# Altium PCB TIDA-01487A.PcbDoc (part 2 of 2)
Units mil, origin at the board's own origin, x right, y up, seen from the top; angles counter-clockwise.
Board outline 3500 x 2800 mil, 4 copper layers (Top Layer, GND, VDD, Bottom Layer), stack 61.6 mil thick; 82 components, 45 nets, 239 pads, 112 vias.
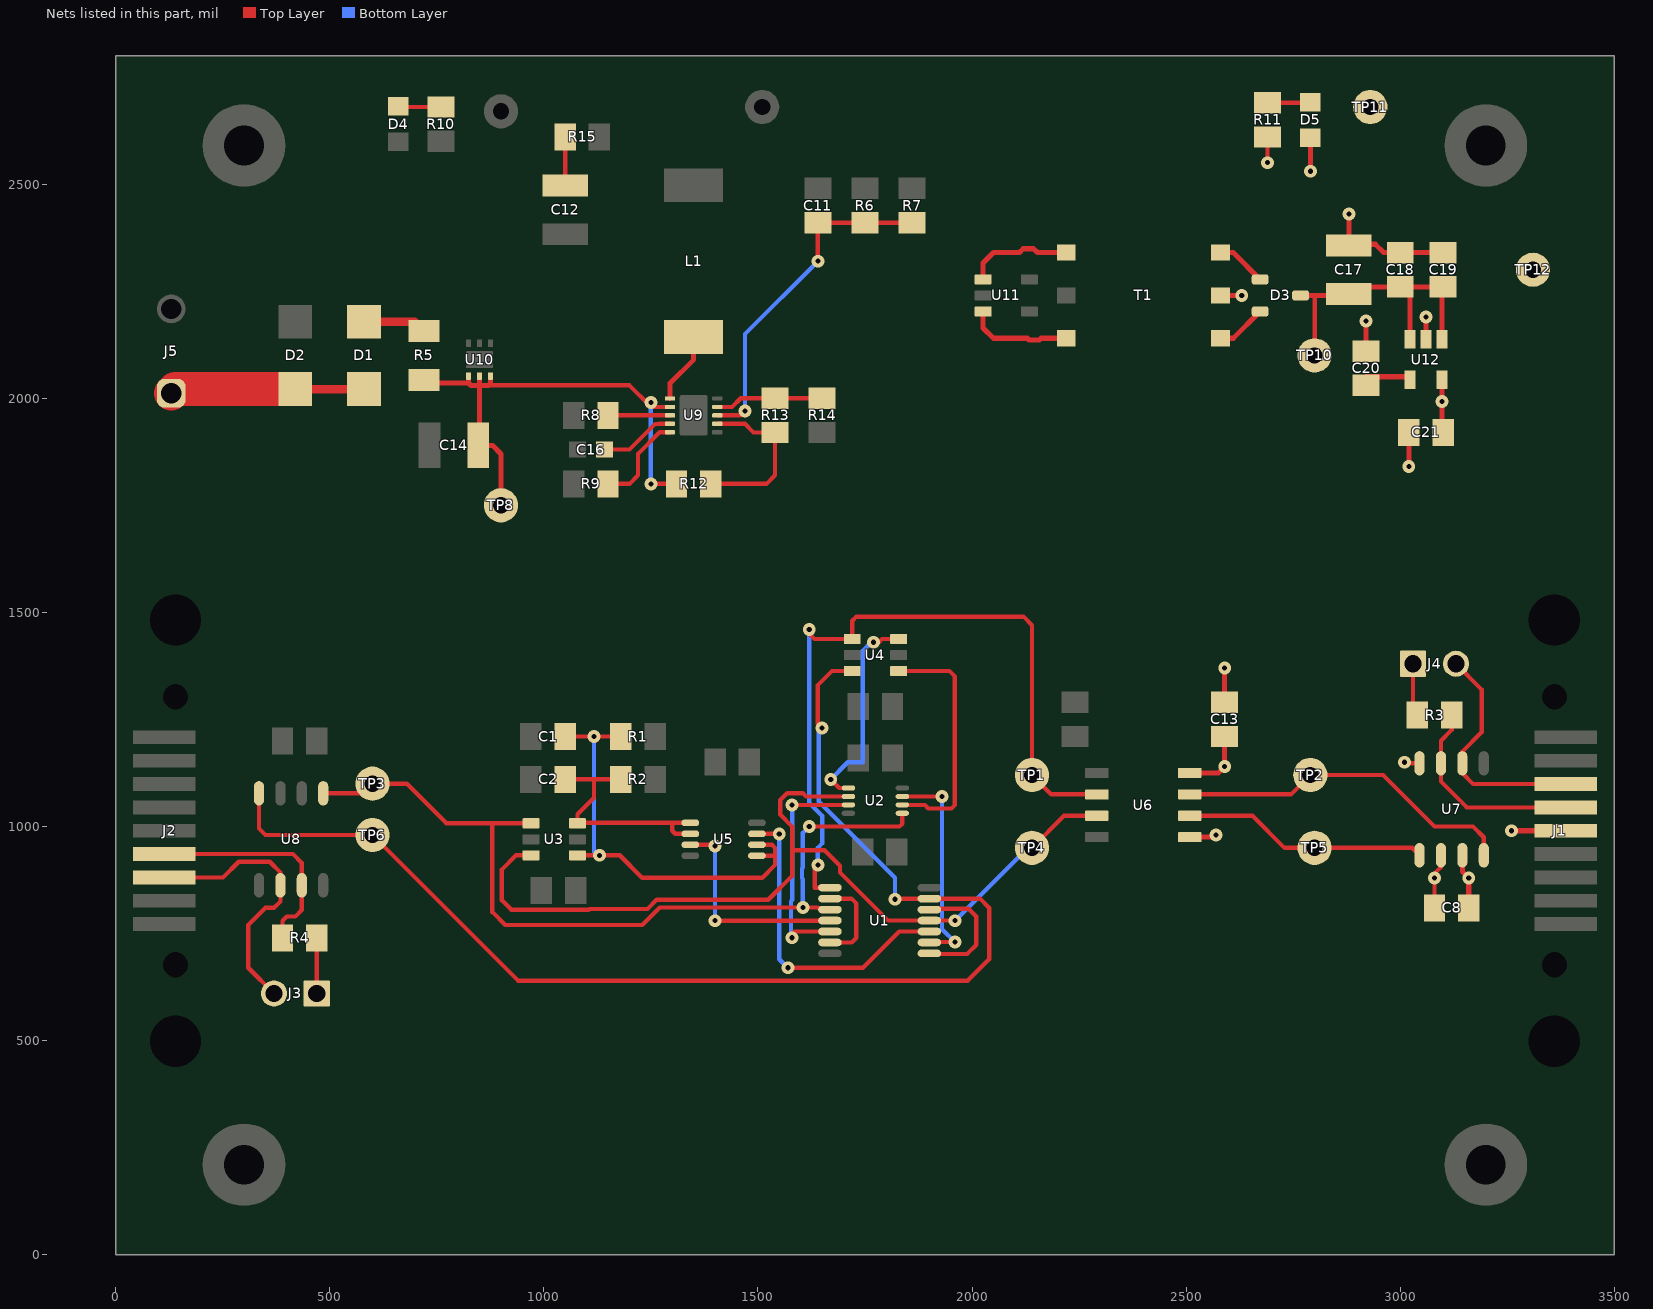
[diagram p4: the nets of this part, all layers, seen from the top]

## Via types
v1: diameter 30, hole 12, Top Layer to Bottom Layer, 79 vias
v2: diameter 39.37, hole 19.68, Top Layer to Bottom Layer, 24 vias
v3: diameter 19.68, hole 7.87, Top Layer to Bottom Layer, 6 vias
v4: diameter 50, hole 20, Top Layer to Bottom Layer, 3 vias

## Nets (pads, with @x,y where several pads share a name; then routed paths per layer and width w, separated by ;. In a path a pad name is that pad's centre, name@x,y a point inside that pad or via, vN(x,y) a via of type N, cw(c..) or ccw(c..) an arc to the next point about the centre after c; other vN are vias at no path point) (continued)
ISO_5V: C8.1 C13.1 C21.1 R11.2 TP11.1 U6.8 U7.3 U12.5 | length 440.7
  Top Layer w10: v1(2690,2550) R11.2@2690,2610
  Top Layer w12: U6.8@2508.27,1125 2575,1125 v1(2590,1140) C13.1@2590,1210 ; U12.5@3097.4,2042.76 v1(3097.4,1992.68) 3097.4,1942.6 C21.1@3100,1940 ; U7.3@3145,932.72 3145,895 v1(3160,880) C8.1@3160,820
ISO_GND: C8.2 C13.2 C17.2 C18.2 C19.2 C20.2 C21.2 D5.1 J1.3 T1.5 TP12.1 U6.5 U7.2 U7.8 U12.2 | length 1077.8
  Top Layer w10: v1(3010,1150) 3012.72,1147.28 U7.8@3045,1147.28 ; C8.2@3080,820 v1(3080,880) 3080,890 3095,905 U7.2@3095,932.72
  Top Layer w12: U6.5@2508.27,975 2565,975 v1(2570,980) ; T1.5@2580,2240 v1(2630,2240) ; C13.2@2590,1290 v1(2590,1370) ; v1(2790,2530) D5.1@2790,2608.66 ; v1(2880,2430) C17.2@2880,2357.09 2882.41,2359.49 2941.72,2359.49 2961.22,2340 C18.2@3000,2340 C19.2@3100,2340 ; C20.2@2920,2130 v1(2920,2180) ; v1(3020,1840.5) C21.2@3020,1920 C21.2@3020,1940 ; U12.2@3060,2137.24 v1(3060,2190) ; v1(3260,990) J1.3@3406,990
NetC1_2: C1.2 R1.1 U3.4 U5.5 U5.6 | length 1015.3
  Top Layer w10: C1.2@1064.41,1210 v1(1117.2,1210) R1.1@1170,1210 ; U3.4@1078.54,932.6 v1(1130,932.6) 1177.4,932.6 1230,880 1510,880 1540,910 1540,950 1532.8,957.2 U5.6@1497.76,957.2 ; U5.5@1497.76,931.61 1538.01,931.61
  Bottom Layer w10: v1(1117.2,1210) 1117.2,935.39 1120,932.6 v1(1130,932.6)
NetC2_2: C2.2 R2.1 U3.6 U5.1 U5.2 | length 551.9
  Top Layer w10: C2.2@1064.41,1110 1117.2,1110 ; R2.1@1170,1110 1117.2,1110 ; U5.2@1342.24,982.8 1307.2,982.8 1300,990 1300,1008.39 ; U5.1@1342.24,1008.39 1300,1008.39 ; 1117.2,1110 1117.2,1067.2 1078.54,1028.54 U3.6@1078.54,1007.4 1079.53,1008.39 1300,1008.39
NetC11_2: C11.2 R6.1 R7.2 U9.8 | length 809.4
  Top Layer w10: U9.8@1405.12,1960 1460,1960 v1(1470,1970) v1@1470,1960 ; v1(1640,2320) C11.2@1640,2410 R7.2@1860,2410
  Bottom Layer w10: v1(1470,1970) 1470,2150 v1(1640,2320)
NetC12_1: C12.1 R15.1 | length 112.9
  Top Layer w10: C12.1@1050,2497.09 R15.1@1050,2610
NetC14_1: C14.1 R5.2 R12.1 TP8.1 U9.2 U10.4 U10.5 U10.6 | length 1227.3
  Top Layer w10: 871.18,2030 1200,2030 v1@1245,1985 ; v1(1250,1800) R12.1@1310,1800 ; v1@1250.31,1979.69 U9.2@1294.88,1979.69
  Top Layer w12: R5.2@720,2042.91 727.32,2035.59 824.41,2035.59 ; U10.4@824.41,2051.61 824.41,2035.59 ; U10.5@850,2051.61 850,2030 ; U10.6@875.59,2051.61 875.59,2034.41 871.18,2030 850,2030 ; TP8.1@900,1750 900,1870 880,1890 C14.1@847.09,1890 850,1892.91 850,2030 ; 824.41,2035.59 830,2030 850,2030
  Bottom Layer w10: v1(1250,1800) 1250,1979.37 1250.31,1979.69 1250.31,1989.69 v1(1250,1990)
NetC16_1: C16.1 U9.4 | length 178.4
  Top Layer w10: C16.1@1141.5,1880 1200,1880 1260,1940 1270,1940 1270.32,1940.32 U9.4@1294.88,1940.32
NetC17_1: C17.1 C18.1 C19.1 D3.3 TP10.1 U12.1 U12.3 | length 737
  Top Layer w10: TP10.1@2800,2100 2800,2240
  Top Layer w12: D3.3@2767.24,2240 2800,2240 2877.09,2240 C17.1@2880,2242.91 2897.09,2260 C18.1@3000,2260 ; U12.3@3022.6,2137.24 3022.6,2237.4 C18.1@3000,2260 ; U12.1@3097.4,2137.24 3097.4,2257.4 C19.1@3100,2260 C18.1@3000,2260
NetC20_1: C20.1 U12.4 | length 105.6
  Top Layer w12: C20.1@2920,2050 3015.35,2050 U12.4@3022.6,2042.76
NetD1_1: D1.1 R5.1 | length 149
  Top Layer w20: D1.1@580,2178.74 698.35,2178.74 R5.1@720,2157.09
NetD1_2: D1.2 D2.2 J5.1 | length 454
  Top Layer w20: D2.2@420,2021.26 D1.2@580,2021.26
  Top Layer w80: J5.1@130,2011.57 139.68,2021.26 D2.2@420,2021.26
NetD3_1: D3.1 T1.6 | length 118.7
  Top Layer w12: T1.6@2580,2340 2610.16,2340 D3.1@2672.76,2277.4
NetD3_2: D3.2 T1.4 | length 118.7
  Top Layer w12: T1.4@2580,2140 2610.16,2140 D3.2@2672.76,2202.6
NetD4_2: D4.2 R10.1 | length 100.6
  Top Layer w10: D4.2@660,2681.34 661.34,2680 R10.1@760,2680
NetD5_2: D5.2 R11.1 | length 100.6
  Top Layer w10: R11.1@2690,2690 2788.66,2690 D5.2@2790,2691.34
NetJ1_2: J1.2 J4.2 U7.6 | length 570.7
  Top Layer w10: J4.2@3130,1380 3190,1320 3190,1220 3145,1175 U7.6@3145,1147.28 3145,1124.17 3170.17,1099 J1.2@3406,1099
NetJ1_7: J1.7 R3.2 U7.7 | length 501.4
  Top Layer w10: R3.2@3120,1260 3120,1225 3095,1200 U7.7@3095,1147.28 3095,1105 3155.5,1044.5 J1.7@3406,1044.5
NetJ2_2: J2.2 J3.2 U8.6 | length 646.8
  Top Layer w10: J2.2@114,881 251,881 287.63,917.63 360,917.63 385,892.63 U8.6@385,862.72 385,825 370,810 350,810 310,770 310,670 J3.2@370,610
NetJ2_7: J2.7 R4.2 U8.7 | length 534.8
  Top Layer w10: J2.7@114,935.5 414.5,935.5 435,915 U8.7@435,862.72 435,805 420,790 400,790 390,780 R4.2@390,740
NetJ3_1: J3.1 R4.1 | length 130
  Top Layer w10: J3.1@470,610 R4.1@470,740
NetJ4_1: J4.1 R3.1 | length 124.1
  Top Layer w10: J4.1@3030,1380 3030,1270 R3.1@3040,1260
NetL1_1: L1.1 U9.1 | length 166.3
  Top Layer w12: U9.1@1294.88,1999.37 1294.88,2034.88 1350,2090 L1.1@1350,2142.83
NetR8_2: R8.2 U9.3 | length 144.9
  Top Layer w10: R8.2@1150,1960 U9.3@1294.88,1960
NetR9_2: R9.2 U9.5 | length 224.1
  Top Layer w10: R9.2@1150,1800 1200,1800 1220,1820 1220,1870 1270.63,1920.63 U9.5@1294.88,1920.63
NetR12_2: R12.2 R13.2 U9.7 | length 401.6
  Top Layer w10: R12.2@1390,1800 1520,1800 1540,1820 R13.2@1540,1920 1490,1920 1469.69,1940.31 U9.7@1405.12,1940.31
NetR13_1: R13.1 R14.2 U9.9 | length 253.3
  Top Layer w10: U9.9@1405.12,1979.68 1439.68,1979.68 1460,2000 R13.1@1540,2000 R14.2@1650,2000
NetT1_1: T1.1 U11.1 | length 250.1
  Top Layer w12: U11.1@2025.87,2277.4 2025.87,2315.87 2050,2340 2110.72,2340 2119.77,2349.05 2143.69,2349.05 2152.75,2340 T1.1@2220,2340
NetT1_3: T1.3 U11.3 | length 245.8
  Top Layer w12: U11.3@2025.87,2202.6 2025.87,2164.13 2050,2140 2129.17,2140 2133.04,2136.13 2156.96,2136.13 2160.83,2140 T1.3@2220,2140
NetTP2_1: TP2.1 U6.7 U7.4 | length 807.7
  Top Layer w10: U6.7@2508.27,1075 2745,1075 TP2.1@2790,1120 2960,1120 3080,1000 3170,1000 3195,975 U7.4@3195,932.72
NetTP5_1: TP5.1 U6.6 U7.1 | length 575
  Top Layer w10: U6.6@2508.27,1025 2655,1025 2730,950 TP5.1@2800,950 3027.72,950 U7.1@3045,932.72
NetU1_2: U1.2 U1.6 | length 212.7
  Top Layer w10: U1.6@1668.26,729.13 1719.13,729.13 1730,740 1730,820 1718.51,831.49 U1.2@1668.26,831.49
NetU1_4: U1.4 U5.3 | length 507.3
  Top Layer w10: U5.3@1342.24,957.2 1402.8,957.2 v1(1400,954.41) ; v1(1400,780) 1667.95,780 U1.4@1668.26,780.31
  Bottom Layer w10: v1(1400,780) v1(1400,954.41)
NetU1_5: U1.5 U2.3 | length 547.6
  Top Layer w10: v1(1580,740) 1580,750 1584.72,754.72 U1.5@1668.26,754.72 ; v1(1580,1050) U2.3@1710.94,1050
  Bottom Layer w10: v1@1577.11,1047.11 v1(1580,1050) 1580,828.23 1577.11,825.34 1577.11,742.89 v1(1580,740)
NetU1_8: U1.8 U1.12 | length 304.2
  Top Layer w10: U1.8@1900.55,703.54 1901.96,702.13 1988.59,702.13 2010,723.54 2010,790 1992.13,807.87 1900.55,807.87 U1.12@1900.55,805.9
NetU1_9: U1.9 U2.7 | length 504.9
  Top Layer w10: U2.7@1837.4,1070.16 1837.56,1070 v1(1930,1070) ; U1.9@1900.55,729.13 1901.42,730 v1(1960,730)
  Bottom Layer w10: v1(1930,1070) 1930,760 v1(1960,730)
NetU1_10: U1.10 U5.7 | length 746.2
  Top Layer w10: U5.7@1497.76,982.8 v1(1550,982.8) v1@1557.2,982.8 ; v1(1570,670) 1745.28,670 1830,754.72 U1.10@1900.55,754.72
  Bottom Layer w10: v1(1550,982.8) 1550,690 v1(1570,670)
NetU2_1: U2.1 U4.6 | length 497.6
  Top Layer w10: v1(1670,1110) 1690.16,1089.84 U2.1@1711.42,1089.84 U2.1@1712.32,1088.94 ; v1(1770,1430) 1782.28,1430 1790,1437.72 U4.6@1828.54,1437.72
  Bottom Layer w10: v1(1670,1110) 1710,1150 1744.72,1150 1744.72,1410 1764.72,1430 v1(1770,1430)
NetU2_6: U2.6 U4.4 | length 566.1
  Top Layer w10: U4.4@1828.54,1362.91 1947.09,1362.91 1960,1350 1960,1050 1952.13,1042.13 1897.87,1042.13 1890,1050 1837.87,1050 U2.6@1837.4,1050.47
RX1: TP6.1 U1.13 U4.3 U8.4 | length 2976.3
  Top Layer w10: U8.4@335,1077.28 335,995 350,980 TP6.1@600,980 940,640 1990,640 2040,690 2040,810 2018.51,831.49 U1.13@1900.55,831.49 1821.49,831.49 v1(1820,830) ; v1(1650,1230) 1640,1240 1640,1330 1672.91,1362.91 U4.3@1720.28,1362.91
  Bottom Layer w10: v1@1642.13,1230 1642.13,1057.98 1820,880.11 v1(1820,830)
RX2_: TP1.1 U1.1 U4.1 U6.2 | length 1768.1
  Top Layer w10: v1(1620,1460) 1620,1450 1632.28,1437.72 U4.1@1720.28,1437.72 1720.28,1480.28 1730,1490 2120,1490 2140,1470 TP1.1@2140,1120 2185,1075 U6.2@2291.73,1075 ; v1(1640,910) 1632.92,902.92 1632.92,857.08 U1.1@1668.26,857.08
  Bottom Layer w10: v1(1620,1460) 1620,1430 1620,1054.83 1650,1024.83 1650,960 1640,950 v1(1640,910)
TX1: TP3.1 U1.3 U2.5 U3.1 U8.1 | length 2001.5
  Top Layer w10: U8.1@485,1077.28 577.28,1077.28 TP3.1@600,1100 680,1100 772.6,1007.4 880,1007.4 ; U3.1@970.28,1007.4 880,1007.4 ; v1(1619.98,1000) 1830.87,1000 1837.4,1006.54 U2.5@1837.4,1030.79 ; U1.3@1668.26,805.9 1664.41,809.76 1640.56,809.76 1639.41,810.91 v1(1604.99,810.91) 1270.91,810.91 1230,770 910,770 880,800 880,1007.4
  Bottom Layer w10: v1(1604.99,810.91) 1604.99,877 1602.99,879 1602.99,902.09 1604.99,904.09 1604.99,985.01 v1(1619.98,1000)
TX2_: TP4.1 U1.11 U2.2 U3.3 U6.3 | length 2123.4
  Top Layer w10: U3.3@970.28,932.6 935.2,932.6 902.13,899.53 902.13,827.87 924.37,805.63 1104.74,805.63 1106.52,807.4 1242.12,807.4 1263.51,828.79 1524.38,828.79 1580,884.4 1580,940 ; U2.2@1711.42,1070.16 1612.67,1070.16 1604.96,1077.87 1568.45,1077.87 1552.13,1061.55 1552.13,1027.87 1580,1000 1580,940 ; v1(1960,780) 1959.69,780.31 U1.11@1900.55,780.31 1804.09,780.31 1691.93,892.48 1691.93,908.07 1655.6,944.4 1584.4,944.4 1580,940 ; TP4.1@2140,950 2215,1025 U6.3@2291.73,1025
  Bottom Layer w10: v1(1960,780) 2130,950 TP4.1@2140,950
pads on no net: J1.1 J1.4 J1.5 J1.6 J1.8 J1.9 J1.MH J2.1 J2.4 J2.5 J2.6 J2.8 J2.9 J2.MH MH1.1 MH2.1 MH3.1 MH4.1 U7.5 U8.5 U9.6 U9.11@1340.16,1899.76 U9.11@1340.16,2020.24 U9.11@1350,1935.2 U9.11@1350,1984.8 U9.11@1359.84,1899.76 U9.11@1359.84,2020.24 U10.7@832.28,2090 U10.7@867.72,2090
copper on no net:
  other v2: 300,138.64 3200,138.64 238.2,174.32 361.8,174.32 3138.2,174.32 3261.8,174.32 238.2,245.68 361.8,245.68 3138.2,245.68 3261.8,245.68 300,281.36 3200,281.36 300,2518.64 3200,2518.64 238.2,2554.32 361.8,2554.32 3138.2,2554.32 3261.8,2554.32 238.2,2625.68 361.8,2625.68 3138.2,2625.68 3261.8,2625.68 300,2661.36 3200,2661.36

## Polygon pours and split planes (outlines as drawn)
GND on GND "GND_POUR" (solid, remove dead copper, pour order 0): 0,2800 2240,2800 2240,1450 2240,1420 2320,1340 2320,0 0,0 0,1890
ISO_GND on GND "GNd_POUR" (solid, remove dead copper, pour order 2): 2550,2800 2550,1420 2480,1350 2480,0 3500,0 3500,2800
5V on VDD "VDD_POUR" (solid, remove dead copper, pour order 6): 0,2800 2240,2800 2240,1420 2320,1340 2320,0 0,0 0,1840 426.58,1840 430,1843.42 430,2360 0,2360
ISO_5V on VDD "VDD_ISO_5V_P008" (solid, remove dead copper, pour order 8): 2550,2800 2550,1420 2550,1418.97 2480,1348.97 2480,0 3500,0 3500,2800

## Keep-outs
Keep-Out Layer:
  text ".Layer_Name" at 577,-858.49 h60

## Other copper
Top Layer:
  text ".Layer_Name" at 577,-858.49 h60
GND:
  pour cut-out: 0,2360 430,2360 430,1843.42 0,1843.42
Bottom Layer:
  text ".Layer_Name" at 577,-858.49 h60

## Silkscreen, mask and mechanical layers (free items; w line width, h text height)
Top Overlay:
  region: 2810,360 2510,360 2510,260 2810,260
  text "GND" at 860,2730 h40
  text "5V" at 1420,2640 h40 r90
  text "ISO_5V" at 3030,2630 h40 r90
  text "ISO_GND" at 3230,2360 h40
  text "'.PRJ_Number'.PCB_Rev-" at 1800,280 h108.27
  text ".Layer_Name" at 577,-858.49 h60
Bottom Overlay:
  text ".Layer_Name" at 577,-858.49 h60
Top Paste:
  text ".Layer_Name" at 577,-858.49 h60
Bottom Paste:
  text ".Layer_Name" at 577,-858.49 h60
Top Solder:
  text ".Layer_Name" at 577,-858.49 h60
  text ".Layer_Name" at 577,-858.49 h60
Bottom Solder:
  text ".Layer_Name" at 577,-858.49 h60
Drill Guide:
  text ".Layer_Name" at 577,-858.49 h60
M1 Board Outline:
  lines w10: 3500,-200 3500,2800 0,2800 0,0 3500,0
  text ".Layer_Name" at 577,-858.49 h60
M2 Board Dimensions:
  rectangle: 125,-400 500,-275
  rectangle: 0,-275 125,-150
  lines w7: 0,-275 1000,-275 ; 125,-400 125,-150 ; 250,-400 250,-150 ; 500,-400 500,-150 ; 750,-400 750,-150 ; 0,-400 0,-150 1000,-150 1000,-400 0,-400
  text ".Layer_Name" at 577,-858.49 h60
M3 3D STEP Top:
  text ".Layer_Name" at 577,-858.49 h60
M4 3D STEP Bottom:
  text ".Layer_Name" at 577,-858.49 h60
M5 Assembly Top:
  lines w10: -292,-930.17 6308,-930.17 ; -292,-726.83 6310,-726.83 ; -292,-523.5 -292,-1133.5 3713,-1133.5 6310,-1133.5 6310,-523.5 -291.5,-523.5 -291.5,-1133.5 1284,-1133.5 ; 2173,-1133.5 2173,-523.5 ; 3440,-726.83 3440,-523.5 ; 4280,-726.83 4280,-523.5 ; 4902,-1140 4902,-937.17
  text "COMPONENTS MARKED 'DNP' SHOULD NOT BE POPULATED." at 1153.5,-318.5 h60
  text "ASSEMBLY VARIANT:" at 1153,-434 h60
  text ".VariantName" at 2189,-434 h60
  text "PCB VIEWED FROM TOP SIDE" at -228.5,-655.67 h60
  text "BOARD #:" at 2248,-655.67 h60
  text ".PRJ_Number" at 2793.5,-655.67 h60
  text "REV:" at 3638,-655.67 h60
  text ".PCB_Rev" at 3929.5,-655.67 h60
  text "SVN REV:" at 4476,-655.67 h60
  text ".VersionControl_RevNumber" at 4982,-655.67 h60
  text "TID #:" at 2248,-859 h60
  text ".TID" at 2793.5,-859 h60
  text "PLOT NAME =" at -228.5,-1064.34 h60
  text ".plot_File_Name" at 577,-1064.34 h60
  text "GENERATED    :" at 2250,-1064.34 h60
  text ".Print_Date" at 3119.5,-1064.34 h60
  text ".Print_Time" at 3848.5,-1064.34 h60
  text "TEXAS INSTRUMENTS" at 5113,-1064.34 h60
M6 Assembly Bottom:
  lines w10: -292.5,-727.33 6309.5,-727.33 ; -290.5,-930.67 6309.5,-930.67 ; 1115.5,-1140.5 1115.5,-937.67 ; 1737.5,-727.33 1737.5,-524 ; 2577.5,-727.33 2577.5,-524 ; 3844.5,-1134 3844.5,-524 ; 4733.5,-1134 6309,-1134 6309,-524 -292.5,-524 -292.5,-1134 2304.5,-1134 6309.5,-1134 6309.5,-524
  text "COMPONENTS MARKED 'DNP' SHOULD NOT BE POPULATED." at 6102,-318 h60
  text ".VariantName" at 5058,-434 h60
  text "ASSEMBLY VARIANT:" at 6097,-434 h60
  text ".VersionControl_RevNumber" at 1035.5,-656.17 h60
  text "SVN REV:" at 1541.5,-656.17 h60
  text ".PCB_Rev" at 2088,-656.17 h60
  text "REV:" at 2379.5,-656.17 h60
  text ".PRJ_Number" at 3224,-656.17 h60
  text "BOARD #:" at 3769.5,-656.17 h60
  text "PCB VIEWED FROM BOTTOM SIDE" at 6246,-656.17 h60
  text ".TID" at 3224,-859.5 h60
  text "TID #:" at 3769.5,-859.5 h60
  text "TEXAS INSTRUMENTS" at 904.5,-1064.84 h60
  text ".Print_Time" at 2169,-1064.84 h60
  text ".Print_Date" at 2898,-1064.84 h60
  text "GENERATED    :" at 3767.5,-1064.84 h60
  text ".plot_File_Name" at 5440.5,-1064.84 h60
  text "PLOT NAME =" at 6246,-1064.84 h60
M9 Title Sheet:
  drawing of 57 lines, arcs and shapes, not listed
  text "1" at 739.84,8036.5 h70
  text "2" at 3235.5,8036.5 h70
  text "3" at 5724.84,8036.5 h70
  text "4" at 8231.51,8036.5 h70
  text "5" at 10730.5,8036.5 h70
  text "6" at 13235.5,8036.5 h70
  text "A" at -416.5,6893.5 h70
  text "A" at 14383.5,6893.5 h70
  text "B" at -416.5,4513.5 h70
  text "B" at 14383.5,4513.5 h70
  text "C" at -416.5,2138.5 h70
  text "C" at 14383.5,2138.5 h70
  text "PROJECT TITLE:" at 11343.5,277.5 h45
  text ".PRJ_Title" at 11393.5,144.17 h70
  text "DESIGNED FOR:" at 11343.5,-23.5 h45
  text ".PRJ_Customer" at 11393.5,-163.5 h70
  text "D" at -416.5,-231.5 h70
  text "D" at 14383.5,-231.5 h70
  text "FILE NAME:" at 11343.5,-323.5 h45
  text ".PCB_File_Name_No_Path" at 11393.5,-443.5 h70
  text "Texas Instruments (TI) and/or its licensors do not warrant the accuracy or completeness of this specification" at 6374,-605.34 h45
  text "ENGINEER:" at 11343.5,-613.5 h45
  text "LAYOUT BY:" at 12848.5,-613.5 h45
  text "or any information contained therein. TI and/or its licensors do not warrant that this design will meet" at 6329.01,-718 h45
  text ".PRJ_Engineer" at 11393.5,-768.49 h70
  text ".PCB_Layout" at 12899,-768.49 h70
  text "the specifications, will be suitable for your application or fit for any particular purpose, or will operate in" at 6329.01,-830.67 h45
  text ".Layer_Name" at 577,-858.49 h60
  text "ALTIUM DESIGNER VERSION:" at 12848.5,-923.5 h45
  text "an implementation. TI and/or its licensors do not warrant that the design is production worthy. You should" at 6329.01,-943.33 h45
  text "completely validate and test your design implementation to confirm the system functionality for your application." at 6374,-1056 h45
  text ".print_Scale" at 11393.5,-1056.83 h70
  text ".Application_BuildNumber" at 12899,-1056.83 h70
  text "1" at 739.84,-1263.5 h70
  text "2" at 3235.5,-1263.5 h70
  text "3" at 5724.84,-1263.5 h70
  text "4" at 8231.51,-1263.5 h70
  text "5" at 10730.5,-1263.5 h70
  text "6" at 13235.5,-1263.5 h70
M10 Fab Notes:
  drawing of 173 lines, arcs and shapes, not listed
  text "DESIGN INFORMATION" at 12378.02,6201 h60
  text "MIN. TRACK WIDTH:" at 11733.46,6021 h60
  text "8" at 12829.7,6021 h60
  text "MIL" at 12984.46,6021 h60
  text "MIN. CLEARANCE:" at 11733.46,5889 h60
  text "0.2" at 12769.7,5889 h60
  text "mm" at 12984.46,5889 h60
  text "MIN. VIA PAD SIZE:" at 11733.46,5757 h60
  text "24" at 12799.71,5757 h60
  text "MIL" at 12984.46,5757 h60
  text "0.05mm (2MIL)" at 12428.46,5615.29 h60
  text "MINIMUM ANNULAR RING" at 11404.23,5611 h60
  text "EXTERNAL" at 13136.46,5611 h60
  text "PER" at 11604.23,5493 h60
  text "IPC-D-275 CLASS 2 LEVEL C" at 11824.23,5493 h60
  text "MIL, HOLES" at 13312.46,5380.71 h60
  text "+/-" at 12920,5380 h60
  text "+/-" at 13774,5380 h60
  text "REGISTRATION TOLERANCES:" at 11404.23,5375 h60
  text "METAL" at 12604,5375 h60
  text "5" at 13180.2,5375 h60
  text "3" at 14013.2,5375 h60
  text "MIL" at 14129.46,5375 h60
  text "+/-" at 13774,5262 h60
  text "HOLE SIZE TOLERANCE (UNLESS OTHERWISE SPECIFIED):" at 11404.23,5257 h60
  text "3" at 14013.2,5257 h60
  text "MIL" at 14129.46,5257 h60
  text "MATERIAL:" at 11329.46,5047.54 h60
  text "FR-4 High Tg" at 12315.9,4907.21 h60
  text "FR-408" at 11750.46,4898.64 h60
  text "OTHER" at 13238.46,4898.64 h60
  text "X" at 12161,4895 h60
  text "62 MIL (1.6mm) +/-10%" at 12070.56,4735.92 h60
  text "THICKNESS:" at 11404.23,4731.64 h60
  text "X" at 11942.4,4731.64 h60
  text "OTHER" at 13355.46,4731.64 h60
  text "TOLERANCE:" at 11404.23,4573.64 h60
  text "X" at 12243.53,4573.64 h60
  text "ANSI IPC-6012 TYPE 3 CLASS 2" at 12430.48,4573.64 h60
  text "OTHER +/-" at 12430.46,4417.64 h60
  text "BOW & TWIST:" at 11404.23,4260.64 h60
  text "X" at 12243.53,4260.64 h60
  text "ANSI IPC-6012 TYPE 3 CLASS 2" at 12430.48,4260.64 h60
  text "OTHER +/-" at 12430.46,4102.13 h60
  text "DRILLING:" at 11329.46,3963.64 h60
  text "REFERENCE:" at 11404.23,3846.64 h60
  text "X" at 12052.46,3846.64 h60
  text "AS SHOWN" at 12239.46,3846.64 h60
  text "X" at 12953.46,3846.64 h60
  text "NC_DRILL FILES" at 13090.46,3846.64 h60
  text "PTH COPPER THICKNESS:" at 11404.23,3688.64 h60
  text "X" at 12534.46,3688.64 h60
  text "20-30 um" at 12671.46,3688.64 h60
  text "OTHER" at 13388.46,3688.64 h60
  text "BOARD FINISH:" at 11329.46,3529.64 h60
  text "SILKSCREEN:" at 11484.68,3411.64 h60
  text "X" at 12433.46,3411.64 h60
  text "TOP" at 12559.46,3411.64 h60
  text "X" at 12943.46,3411.64 h60
  text "BOTTOM" at 13070.46,3411.64 h60
  text "SILKSCREEN COLOR:" at 11484.68,3244.64 h60
  text "X" at 12432.42,3244.64 h60
  text "WHITE" at 12559.46,3244.64 h60
  text "OTHER" at 13070.46,3244.64 h60
  text "X" at 12563.42,3085.44 h60
  text "GREEN" at 12690.46,3085.44 h60
  text "OTHER" at 13308.46,3085.44 h60
  text "SOLDER RESIST COLOR:" at 11484.68,3074.64 h60
  text "X" at 12563.42,2915.44 h60
  text "MATTE" at 12690.46,2915.44 h60
  text "SEMI-GLOSS" at 13308,2914.8 h60
  text "IMMERSION GOLD (ENIG)" at 12390.46,2726.92 h60
  text "ENEPIG" at 13728,2723.64 h60
  text "SURFACE FINISH:" at 11329.46,2722.64 h60
  text "X" at 12203.51,2722.64 h60
  text "IMM. TIN/SILVER OR EQUIV" at 11659,2565.64 h60
  text "OTHER" at 13090.46,2565.64 h60
  text "ARRAY/PANEL:" at 11329.46,2386.64 h60
  text "CUT AND TRIM PER M1 BOARD OUTLINE" at 12390.46,2382.35 h60
  text "N.C. ROUTE" at 12390.46,2230.64 h60
  text "X" at 13069.46,2230.64 h60
  text "V. SCORE" at 13256.46,2230.64 h60
  text "CERTIFICATION:" at 11329.46,2093.64 h60
  text "MATERIALS AND WORKMANSHIP FOR ALL PCBS" at 12054.46,2093.64 h60
  text "TO MEET OR EXCEED THE REQUIREMENTS OF:" at 12054.46,1995.64 h60
  text "X" at 11680.96,1859.13 h60
  text "ANSI IPC-A-600F CLASS ->" at 11819.96,1859.13 h60
  text "X" at 13459.02,1859.13 h60
  text "2" at 13577.96,1859.14 h60
  text "1" at 13262.96,1857.64 h60
  text "3" at 13931.96,1857.64 h60
  text "X" at 12495.02,1699.64 h60
  text "RoHS" at 12631.96,1699.64 h60
  text "OTHER" at 13276.36,1699.64 h60
  text "PER ORDER" at 13673.42,1699.64 h60
  text "ALL BOARDS MUST MEET OR EXCEED UL94-V0 REQUIREMENTS." at 11357,1534 h60
  text "PCB MUST BEAR THE UL94V-0 UL REGISTERED MATERIAL ID NUMBER" at 11357,1414 h60
  text "ADDITIONAL REQUIREMENTS:" at 11329.46,1240.64 h60
  text "MICROSECTION:" at 11404.23,1125.64 h60
  text "YES" at 12309.96,1125.64 h60
  text "REQUIRED" at 13171.46,969.49 h60
  text "BARE BOARD ELEC. TEST:" at 11404.23,966.64 h60
  text "NONE" at 12709.96,966.64 h60
  text "X" at 13044.46,966.64 h60
  text "PER ORDER" at 13763.46,966.64 h60
  text ".Layer_Name" at 577,-858.49 h60
M11 Gerber Information:
  lines w10: -292,-930.17 6308,-930.17 ; -292,-726.83 6310,-726.83 ; -292,-523.5 -292,-1133.5 3713,-1133.5 6310,-1133.5 6310,-523.5 -291.5,-523.5 -291.5,-1133.5 1284,-1133.5 ; 2173,-1133.5 2173,-523.5 ; 3440,-726.83 3440,-523.5 ; 4280,-726.83 4280,-523.5 ; 4902,-1140 4902,-937.17
  text "ALL ARTWORK VIEWED FROM TOP SIDE" at -228.5,-655.67 h60
  text "BOARD #:" at 2248,-655.67 h60
  text ".PRJ_Number" at 2793.5,-655.67 h60
  text "REV:" at 3638,-655.67 h60
  text ".PCB_Rev" at 3929.5,-655.67 h60
  text "SVN REV:" at 4476,-655.67 h60
  text ".VersionControl_RevNumber" at 4982,-655.67 h60
  text "LAYER NAME =" at -228.5,-858.49 h60
  text "TID #:" at 2248,-859 h60
  text ".TID" at 2793.5,-859 h60
  text "PLOT NAME =" at -228.5,-1064.34 h60
  text ".plot_File_Name" at 577,-1064.34 h60
  text "GENERATED    :" at 2250,-1064.34 h60
  text ".Print_Date" at 3119.5,-1064.34 h60
  text ".Print_Time" at 3848.5,-1064.34 h60
  text "TEXAS INSTRUMENTS" at 5113,-1064.34 h60
M12 Stackup:
  drawing of 295 lines, arcs and shapes, not listed
  text "Layer" at 9797.84,7830 h60
  text "Name" at 10207.76,7830 h60
  text "Material" at 11137.5,7830 h60
  text "Thickness" at 11997.27,7830 h60
  text "Constant" at 12647.1,7830 h60
  text "Board Layer Stack" at 13216.96,7830 h60
  text "1" at 9797.84,7710 h60
  text "Top Overlay" at 10207.76,7710 h60
  text "2" at 9797.84,7590 h60
  text "Top Solder" at 10207.76,7590 h60
  text "Solder Resist" at 11137.5,7590 h60
  text "0.40mil" at 11997.27,7590 h60
  text "3.5" at 12647.1,7590 h60
  text "3" at 9797.84,7470 h60
  text "Top Layer" at 10207.76,7470 h60
  text "Copper" at 11137.5,7470 h60
  text "1.40mil" at 11997.27,7470 h60
  text "4" at 9797.84,7350 h60
  text "Dielectric1" at 10207.76,7350 h60
  text "FR-4" at 11137.5,7350 h60
  text "8.00mil" at 11997.27,7350 h60
  text "4.8" at 12647.1,7350 h60
  text "5" at 9797.84,7230 h60
  text "GND" at 10207.76,7230 h60
  text "Copper" at 11137.5,7230 h60
  text "1.40mil" at 11997.27,7230 h60
  text "6" at 9797.84,7110 h60
  text "Dielectric 2" at 10207.76,7110 h60
  text "FR-4" at 11137.5,7110 h60
  text "40.00mil" at 11997.27,7110 h60
  text "4.2" at 12647.1,7110 h60
  text "7" at 9797.84,6990 h60
  text "VDD" at 10207.76,6990 h60
  text "Copper" at 11137.5,6990 h60
  text "1.40mil" at 11997.27,6990 h60
  text "8" at 9797.84,6870 h60
  text "Dielectric 3" at 10207.76,6870 h60
  text "8.00mil" at 11997.27,6870 h60
  text "4.2" at 12647.1,6870 h60
  text "9" at 9797.84,6750 h60
  text "Bottom Layer" at 10207.76,6750 h60
  text "Copper" at 11137.5,6750 h60
  text "1.40mil" at 11997.27,6750 h60
  text "10" at 9797.84,6630 h60
  text "Bottom Solder" at 10207.76,6630 h60
  text "Solder Resist" at 11137.5,6630 h60
  text "0.40mil" at 11997.27,6630 h60
  text "3.5" at 12647.1,6630 h60
  text "11" at 9797.84,6510 h60
  text "Bottom Overlay" at 10207.76,6510 h60
  text ".Layer_Name" at 577,-858.49 h60
M13 Component Bodies Top:
  text ".Layer_Name" at 577,-858.49 h60
M14 Component Bodies Bottom:
  text ".Layer_Name" at 577,-858.49 h60
M15 Courtyards Top:
  text ".Layer_Name" at 577,-858.49 h60
M16 Courtyards Bottom:
  text ".Layer_Name" at 577,-858.49 h60
Drill Drawing:
  circle w10: c5348.9,2406.15 r22.14
  lines w10: 5326.76,2527.92 5371.04,2527.92 5348.9,2483.64 5326.76,2527.92 ; 5326.76,2594.33 5337.83,2594.33 5337.83,2583.26 5359.97,2583.26 5359.97,2594.33 5371.04,2594.33 5371.04,2616.47 5359.97,2616.47 5359.97,2627.54 5337.83,2627.54 5337.83,2616.47 5326.76,2616.47 5326.76,2594.33 ; 5326.76,2682.89 5371.04,2682.89 5371.04,2727.17 5326.76,2727.17 5326.76,2682.89 ; 5326.76,2793.58 5337.83,2793.58 5348.9,2782.51 5359.97,2793.58 5371.04,2793.58 5359.97,2804.65 5371.04,2815.72 5359.97,2815.72 5348.9,2826.79 5337.83,2815.72 5326.76,2815.72 5337.83,2804.65 5326.76,2793.58 ; 5326.76,2882.14 5371.04,2882.14 5371.04,2926.42 5326.76,2926.42 5326.76,2882.14 ; 5326.76,3026.04 5371.04,3026.04 5348.9,2981.76 5326.76,3026.04 ; 5326.76,3081.39 5326.76,3092.46 5337.83,3103.53 5326.76,3114.6 5326.76,3125.67 5337.83,3125.67 5348.9,3114.6 5359.97,3125.67 5371.04,3125.67 5371.04,3114.6 5359.97,3103.53 5371.04,3092.46 5371.04,3081.39 5359.97,3081.39 5348.9,3092.46 5337.83,3081.39 5326.76,3081.39 ; 5326.76,3192.08 5337.83,3192.08 5348.9,3181.01 5359.97,3192.08 5371.04,3192.08 5359.97,3203.15 5371.04,3214.22 5359.97,3214.22 5348.9,3225.29 5337.83,3214.22 5326.76,3214.22 5337.83,3203.15 5326.76,3192.08 ; 5326.76,3280.64 5348.9,3291.71 5371.04,3280.64 5359.97,3302.78 5371.04,3324.92 5348.9,3313.85 5326.76,3324.92 5337.83,3302.78 5326.76,3280.64 ; 5335.62,2798.01 5342.26,2798.01 5348.9,2791.37 5355.54,2798.01 5362.18,2798.01 5355.54,2804.65 5362.18,2811.29 5355.54,2811.29 5348.9,2817.93 5342.26,2811.29 5335.62,2811.29 5342.26,2804.65 5335.62,2798.01 ; 5335.62,2890.99 5362.18,2890.99 5362.18,2917.56 5335.62,2917.56 5335.62,2890.99 ; 5335.62,3017.18 5362.18,3017.18 5348.9,2990.62 5335.62,3017.18
  lines w12: 5286,2354.12 8398.79,2354.12 ; 5286,3350.38 8398.79,3350.38 ; 5601.62,2254.5 5601.62,3450 ; 5918.86,2254.5 5918.86,3450 ; 6540.41,2254.5 6540.41,3450 ; 6784.69,2254.5 6784.69,3450 ; 7145,2254.5 7145,3450 ; 7854.63,2254.5 7854.63,3450 ; 5286,2254.5 8398.79,2254.5 8398.79,3450 5286,3450 5286,2254.5
  text "Symbol" at 5345.77,3380.26 h72
  text "Quantity" at 5631.51,3380.26 h72
  text "Finished Hole Size" at 5948.74,3380.26 h72
  text "Plated" at 6570.3,3380.26 h72
  text "Hole Type" at 6814.57,3380.26 h72
  text "Drill Layer Pair" at 7174.89,3380.26 h72
  text "Hole Tolerance" at 7884.51,3380.26 h72
  text "4" at 5631.51,3280.64 h60
  text "59.00mil (1.499mm)" at 5948.74,3280.64 h60
  text "NPTH" at 6570.3,3280.64 h60
  text "Round" at 6814.57,3280.64 h60
  text "Top Layer - Bottom Layer" at 7174.89,3280.64 h60
  text "4" at 5631.51,3181.01 h60
  text "120.00mil (3.048mm)" at 5948.74,3181.01 h60
  text "NPTH" at 6570.3,3181.01 h60
  text "Round" at 6814.57,3181.01 h60
  text "Top Layer - Bottom Layer" at 7174.89,3181.01 h60
  text "6" at 5631.51,3081.39 h60
  text "7.87mil (0.200mm)" at 5948.74,3081.39 h60
  text "PTH" at 6570.3,3081.39 h60
  text "Round" at 6814.57,3081.39 h60
  text "Top Layer - Bottom Layer" at 7174.89,3081.39 h60
  text "79" at 5631.51,2981.76 h60
  text "12.00mil (0.305mm)" at 5948.74,2981.76 h60
  text "PTH" at 6570.3,2981.76 h60
  text "Round" at 6814.57,2981.76 h60
  text "Top Layer - Bottom Layer" at 7174.89,2981.76 h60
  text "24" at 5631.51,2882.14 h60
  text "19.69mil (0.500mm)" at 5948.74,2882.14 h60
  text "PTH" at 6570.3,2882.14 h60
  text "Round" at 6814.57,2882.14 h60
  text "Top Layer - Bottom Layer" at 7174.89,2882.14 h60
  text "3" at 5631.51,2782.51 h60
  text "20.00mil (0.508mm)" at 5948.74,2782.51 h60
  text "PTH" at 6570.3,2782.51 h60
  text "Round" at 6814.57,2782.51 h60
  text "Top Layer - Bottom Layer" at 7174.89,2782.51 h60
  text "12" at 5631.51,2682.89 h60
  text "37.99mil (0.965mm)" at 5948.74,2682.89 h60
  text "PTH" at 6570.3,2682.89 h60
  text "Round" at 6814.57,2682.89 h60
  text "Top Layer - Bottom Layer" at 7174.89,2682.89 h60
  text "4" at 5631.51,2583.26 h60
  text "40.16mil (1.020mm)" at 5948.74,2583.26 h60
  text "PTH" at 6570.3,2583.26 h60
  text "Round" at 6814.57,2583.26 h60
  text "Top Layer - Bottom Layer" at 7174.89,2583.26 h60
  text "2" at 5631.51,2483.64 h60
  text "47.24mil (1.200mm)" at 5948.74,2483.64 h60
  text "PTH" at 6570.3,2483.64 h60
  text "Round" at 6814.57,2483.64 h60
  text "Top Layer - Bottom Layer" at 7174.89,2483.64 h60
  text "4" at 5631.51,2384.01 h60
  text "92.52mil (2.350mm)" at 5948.74,2384.01 h60
  text "PTH" at 6570.3,2384.01 h60
  text "Round" at 6814.57,2384.01 h60
  text "Top Layer - Bottom Layer" at 7174.89,2384.01 h60
  text "142 Total" at 5631.51,2284.39 h60
  text ".Layer_Name" at 577,-858.49 h60
M17 Embedded Cavity:
  text ".Layer_Name" at 577,-858.49 h60
M18 Embedded Assembly:
  text ".Layer_Name" at 577,-858.49 h60
M19 Embedded Keepout:
  text ".Layer_Name" at 577,-858.49 h60

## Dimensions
0,0 to 3500,0 on M2 Board Dimensions
0,0 to 3500,2800 on M2 Board Dimensions
0,-400 to 1000,-400 on M2 Board Dimensions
